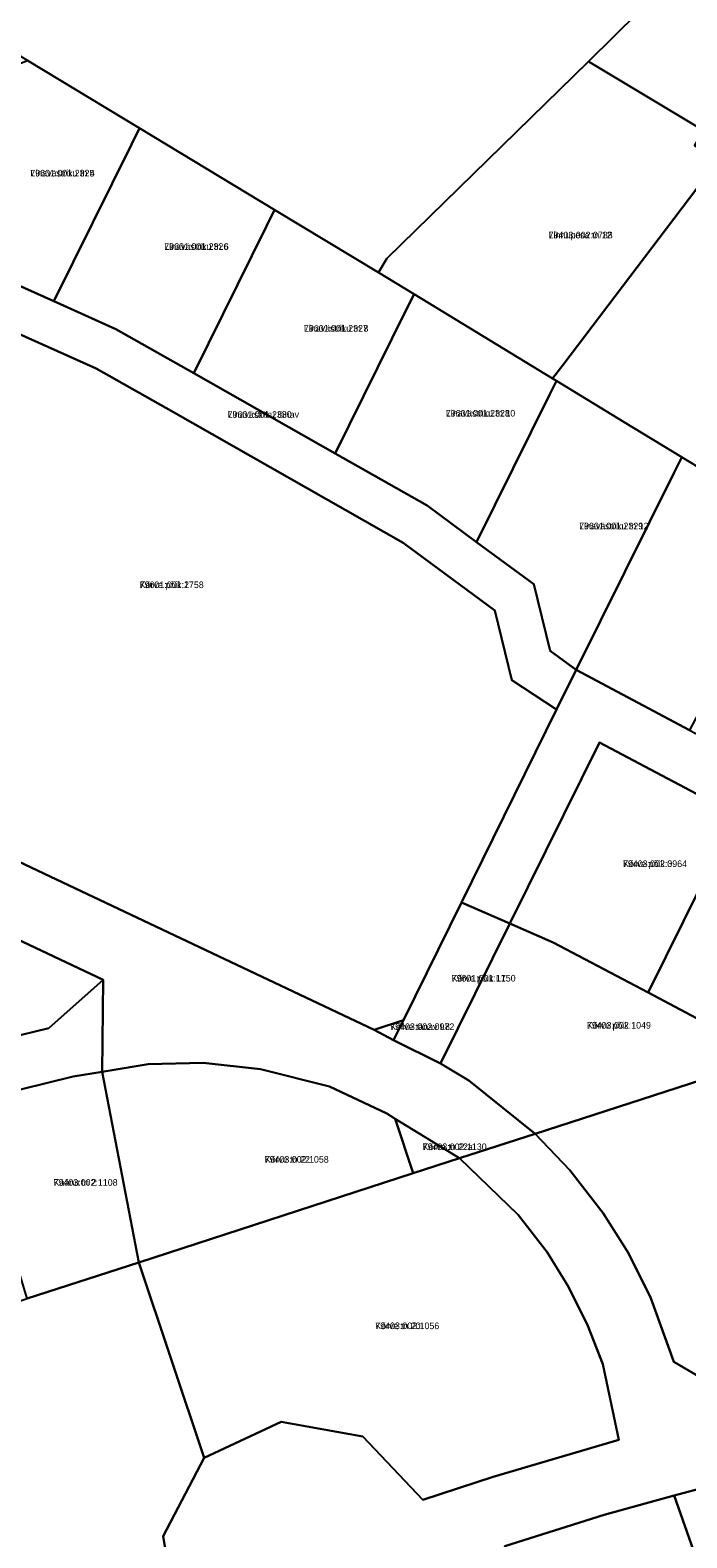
# Model space of a CAD drawing. Extents: x 625111 to 706696, y 6474150 to 6504223.
# Drawn here: x 660873.5 to 661022.2, y 6478536.3 to 6478877.8 of the extents above; entities that cross this region are included whole.
import ezdxf

# ---------------------------------------------------------------- set-up
doc = ezdxf.new("R2010")
doc.units = 0
for name, color, linetype in [('L_AADRESS', 7, 'Continuous'), ('PIIR', 7, 'Continuous'), ('TUNNUS', 7, 'Continuous')]:
    doc.layers.add(name, color=color, linetype=linetype)

msp = doc.modelspace()

# ---------------------------------------------------------------- linework, layer by layer
at = {"layer": 'PIIR'}
for points in [[(660986.89, 6478959.98), (661086.27, 6478955.62), (661056.26, 6478926.11), (661034.15, 6478904.56), (660999.96, 6478870.7), (660954.3, 6478826.09), (660952.37, 6478822.91), (660928.87, 6478837.12), (660898.29, 6478855.61), (660872.92, 6478870.95), (660852.55, 6478883.09), (660858.41, 6478883.66), (660875.82, 6478885.33), (660920.63, 6478966.93), (660928, 6478962.52), (660980.45, 6478960.29)], [(661067.24, 6478893.28), (661039.56, 6478860.62), (661030.64, 6478865.17), (661026.03, 6478855.14), (660999.96, 6478870.7), (661034.15, 6478904.56)], [(660867.8, 6478869.03), (660872.92, 6478870.95), (660898.29, 6478855.61), (660896.46, 6478851.92), (660878.87, 6478816.41), (660848.79, 6478829.88)], [(660999.96, 6478870.7), (661026.03, 6478855.14), (661024, 6478851.68), (661029.5, 6478848.51), (660994.14, 6478801.97), (660991.81, 6478798.9), (660960.45, 6478817.99), (660952.37, 6478822.91), (660954.3, 6478826.09)], [(660780.06, 6478852.99), (660790.29, 6478856.06), (660848.79, 6478829.88), (660878.87, 6478816.41), (660892.91, 6478810.13), (660910.55, 6478800.09), (660942.6, 6478781.91), (660963.41, 6478770.11), (660974.61, 6478761.86), (660987.61, 6478752.31), (660991.27, 6478737.19), (660997.16, 6478732.88), (660992.72, 6478723.96), (660982.6, 6478730.57), (660978.75, 6478746.39), (660957.98, 6478761.68), (660905.93, 6478791.27), (660888.46, 6478801.19), (660776.16, 6478851.48)], [(660896.46, 6478851.92), (660898.29, 6478855.61), (660928.87, 6478837.12), (660927.06, 6478833.46), (660910.55, 6478800.09), (660892.91, 6478810.13), (660878.87, 6478816.41)], [(660786.66, 6478828.41), (660776.16, 6478851.48), (660888.46, 6478801.19), (660905.93, 6478791.27), (660957.98, 6478761.68), (660978.75, 6478746.39), (660982.6, 6478730.57), (660992.72, 6478723.96), (660971.16, 6478680.21), (660958.02, 6478653.57), (660951.39, 6478651.38), (660815.72, 6478715.52), (660830.59, 6478747.14), (660825.54, 6478750.74), (660819.25, 6478756.03), (660811.43, 6478764.86), (660807.92, 6478770.76), (660805.17, 6478774.97), (660798.35, 6478790.88), (660792.68, 6478809.19)], [(660994.14, 6478801.97), (661029.5, 6478848.51), (661058.3, 6478832.1), (661055.96, 6478787.12), (661037.01, 6478775.91), (661034.99, 6478772.61), (661021.08, 6478781.08), (661008.03, 6478789.02), (660992.69, 6478798.36), (660991.81, 6478798.9)], [(660927.06, 6478833.46), (660928.87, 6478837.12), (660952.37, 6478822.91), (660960.45, 6478817.99), (660958.62, 6478814.29), (660942.6, 6478781.91), (660910.55, 6478800.09)], [(660958.62, 6478814.29), (660960.45, 6478817.99), (660991.81, 6478798.9), (660992.69, 6478798.36), (660991.12, 6478795.18), (660974.61, 6478761.86), (660963.41, 6478770.11), (660942.6, 6478781.91)], [(660991.12, 6478795.18), (660992.69, 6478798.36), (661008.03, 6478789.02), (661021.08, 6478781.08), (661019.3, 6478777.5), (660997.16, 6478732.88), (660991.27, 6478737.19), (660987.61, 6478752.31), (660974.61, 6478761.86)], [(660997.16, 6478732.88), (661019.3, 6478777.5), (661021.08, 6478781.08), (661034.99, 6478772.61), (661047.14, 6478765.21), (661045.26, 6478761.67), (661022.82, 6478719.26)], [(660971.16, 6478680.21), (660992.72, 6478723.96), (660997.16, 6478732.88), (661022.82, 6478719.26), (661049.33, 6478705.22), (661073.73, 6478692.3), (661098.9, 6478678.98), (661103.34, 6478665.29), (661080.51, 6478657.88), (661073.75, 6478678.73), (661033.4, 6478700.09), (661002.47, 6478716.46), (660982.13, 6478675.44)], [(660982.13, 6478675.44), (661002.47, 6478716.46), (661033.4, 6478700.09), (661013.47, 6478659.79), (660991.97, 6478671.16)], [(661013.47, 6478659.79), (661033.4, 6478700.09), (661073.75, 6478678.73), (661080.51, 6478657.88), (661076.94, 6478656.74), (661041.18, 6478645.1)], [(660890.03, 6478662.69), (660877.72, 6478651.74), (660862.2, 6478647.93), (660844.83, 6478642.53), (660834.45, 6478638.58), (660820.5, 6478648.28), (660845.28, 6478683.81)], [(660966.42, 6478643.75), (660955.77, 6478648.99), (660958.02, 6478653.57), (660971.16, 6478680.21), (660982.13, 6478675.44)], [(660966.42, 6478643.75), (660982.13, 6478675.44), (660991.97, 6478671.16), (661013.47, 6478659.79), (661041.18, 6478645.1), (661038.95, 6478644.36), (660987.9, 6478627.82), (660972.85, 6478639.87)], [(660951.39, 6478651.38), (660958.02, 6478653.57), (660955.77, 6478648.99)], [(660889.83, 6478641.84), (660898.11, 6478598.66), (660872.84, 6478590.46), (660859.49, 6478634.52), (660865.42, 6478636.36), (660883.26, 6478640.75)], [(660956.2, 6478631.22), (660960.24, 6478618.84), (660898.11, 6478598.66), (660889.83, 6478641.84), (660900.19, 6478643.55), (660912.68, 6478643.84), (660925.7, 6478642.46), (660941.32, 6478638.49), (660954.3, 6478632.36)], [(661038.95, 6478644.36), (661062.64, 6478571.36), (661047.76, 6478568.51), (661036.47, 6478565.99), (661019.27, 6478576.12), (661014.05, 6478590.57), (661008.99, 6478600.73), (661003.31, 6478609.82), (660995.76, 6478619.58), (660987.9, 6478627.82)], [(660956.2, 6478631.22), (660970.72, 6478622.24), (660960.24, 6478618.84)], [(660970.72, 6478622.24), (660983.99, 6478609.46), (660990.58, 6478600.95), (660995.45, 6478593.15), (660999.84, 6478584.32), (661003.19, 6478575.59), (661006.79, 6478558.48), (660978.33, 6478550.08), (660962.4, 6478544.84), (660948.86, 6478559.2), (660930.35, 6478562.57), (660912.94, 6478554.38), (660898.11, 6478598.66), (660960.24, 6478618.84)], [(660898.11, 6478598.66), (660912.94, 6478554.38), (660903.62, 6478536.65), (660906.71, 6478517.62), (660919.92, 6478504.71), (660900.54, 6478474.94), (660781.43, 6478552.48), (660772.51, 6478558.29), (660821.85, 6478573.9), (660847.58, 6478582.26), (660872.84, 6478590.46)], [(661058.63, 6478554.81), (661086.57, 6478475.33), (661048.84, 6478462.08), (661019.39, 6478545.82), (661026.12, 6478547.66), (661050.95, 6478553.34)], [(661019.39, 6478545.82), (661048.84, 6478462.08), (661011.1, 6478448.82), (660981.01, 6478534.39), (661003.5, 6478541.47)]]:
    msp.add_lwpolyline(points, close=True, dxfattribs=at)
for points in [[(660815.72, 6478715.52), (660951.39, 6478651.38), (660955.77, 6478648.99), (660966.42, 6478643.75), (660972.85, 6478639.87), (660987.9, 6478627.82), (660970.72, 6478622.24), (660956.2, 6478631.22), (660954.3, 6478632.36), (660941.32, 6478638.49), (660925.7, 6478642.46), (660912.68, 6478643.84), (660900.19, 6478643.55), (660889.83, 6478641.84), (660890.03, 6478662.69), (660845.28, 6478683.81)], [(660862.2, 6478647.93), (660877.72, 6478651.74), (660890.03, 6478662.69), (660889.83, 6478641.84), (660883.26, 6478640.75), (660865.42, 6478636.36)], [(660906.71, 6478517.62), (660903.62, 6478536.65), (660912.94, 6478554.38), (660930.35, 6478562.57), (660948.86, 6478559.2), (660962.4, 6478544.84), (660978.33, 6478550.08), (661006.79, 6478558.48), (661003.19, 6478575.59), (660999.84, 6478584.32), (660995.45, 6478593.15), (660990.58, 6478600.95), (660983.99, 6478609.46), (660970.72, 6478622.24), (660987.9, 6478627.82), (660995.76, 6478619.58), (661003.31, 6478609.82), (661008.99, 6478600.73), (661014.05, 6478590.57), (661019.27, 6478576.12), (661036.47, 6478565.99)], [(661026.12, 6478547.66), (661019.39, 6478545.82), (661003.5, 6478541.47), (660981.01, 6478534.39)]]:
    msp.add_lwpolyline(points, dxfattribs=at)

# ---------------------------------------------------------------- texts
at = {"layer": 'L_AADRESS'}
for s, p in [('Linavästriku tn 4', (660873.54, 6478844.69)), ('Linavästriku tn 6', (660903.87, 6478828.06)), ('Linnupesa tn 12', (660990.93, 6478830.66)), ('Linavästriku tn 8', (660935.5, 6478809.52)), ('Linavästriku tänav', (660918.23, 6478790.01)), ('Linavästriku tn 10', (660967.64, 6478790.3)), ('Linavästriku tn 12', (660997.84, 6478764.74)), ('Kõrve põik 2', (660898.31, 6478751.43)), ('Kõrve põik 3', (661007.77, 6478688.23)), ('Kõrve põik L1', (660968.95, 6478662.29)), ('Kõrve tänav L8', (660955.06, 6478651.31)), ('Kõrve põik 1', (660999.59, 6478651.63)), ('Kõrve tn 22a', (660962.39, 6478624.1)), ('Kõrve tn 22', (660926.62, 6478621.25)), ('Käänu tn 2', (660878.8, 6478616.02)), ('Kõrve tn 20', (660951.66, 6478583.54))]:
    msp.add_text(s, height=1.5, dxfattribs=at).set_placement(p)
at = {"layer": 'TUNNUS'}
for s, p in [('79601:001:2325', (660873.54, 6478844.69)), ('79601:001:2326', (660903.87, 6478828.06)), ('79403:002:0788', (660990.93, 6478830.66)), ('79601:001:2327', (660935.5, 6478809.52)), ('79601:001:2330', (660918.23, 6478790.01)), ('79601:001:2328', (660967.64, 6478790.3)), ('79601:001:2329', (660997.84, 6478764.74)), ('79601:001:1758', (660898.31, 6478751.43)), ('79403:002:0964', (661007.77, 6478688.23)), ('79601:001:1750', (660968.95, 6478662.29)), ('79403:002:0972', (660955.06, 6478651.31)), ('79403:002:1049', (660999.59, 6478651.63)), ('79403:002:1130', (660962.39, 6478624.1)), ('79403:002:1058', (660926.62, 6478621.25)), ('79403:002:1108', (660878.8, 6478616.02)), ('79403:002:1056', (660951.66, 6478583.54))]:
    msp.add_text(s, height=1.5, dxfattribs=at).set_placement(p)

doc.saveas('drawing.dxf')
